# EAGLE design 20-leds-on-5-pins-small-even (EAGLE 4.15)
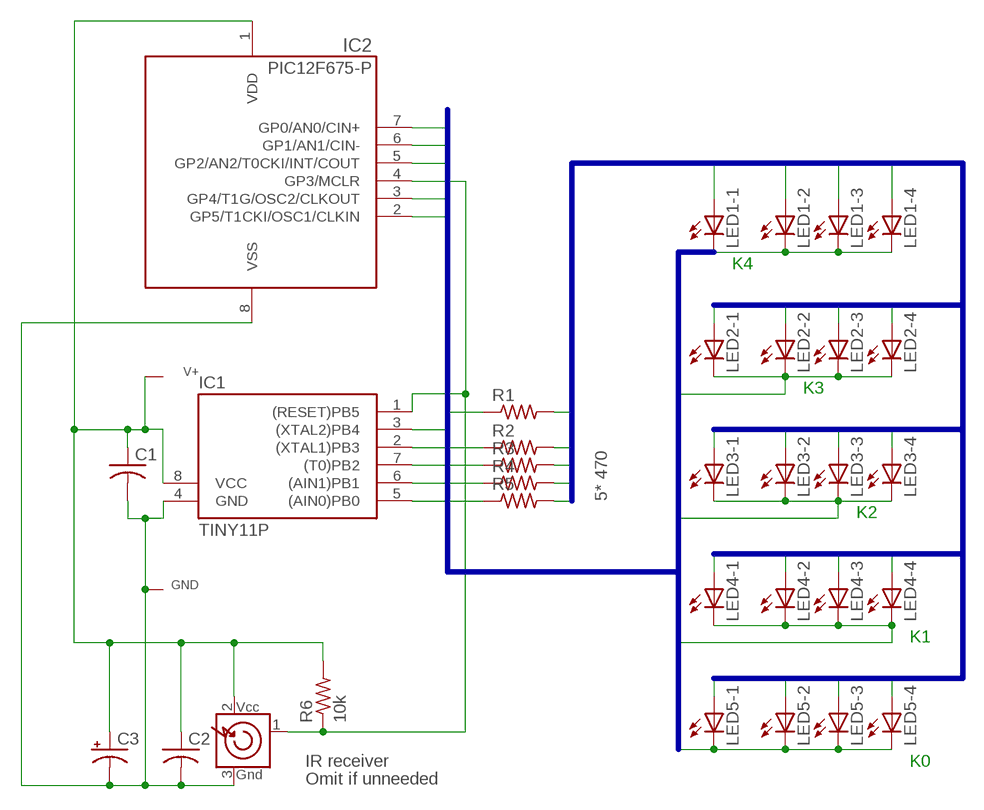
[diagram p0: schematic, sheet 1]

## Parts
C1  C-US075-032X103  [C075-032X103]
C2  C-US050-035X075  [C050-035X075]
C3  CPOL-USE3.5-8  [E3,5-8]
GND  WIRE  [GENERIC1]
IC1  TINY11P  [DIL08]
IC2  PIC12F675-P  [DIP-8]
IRX1  IRRECVV  [IR-RCVR-V]
LED1-1  LED3MM  [LED3MM]
LED1-2  LED3MM  [LED3MM]
LED1-3  LED3MM  [LED3MM]
LED1-4  LED3MM  [LED3MM]
LED2-1  LED3MM  [LED3MM]
LED2-2  LED3MM  [LED3MM]
LED2-3  LED3MM  [LED3MM]
LED2-4  LED3MM  [LED3MM]
LED3-1  LED3MM  [LED3MM]
LED3-2  LED3MM  [LED3MM]
LED3-3  LED3MM  [LED3MM]
LED3-4  LED3MM  [LED3MM]
LED4-1  LED3MM  [LED3MM]
LED4-2  LED3MM  [LED3MM]
LED4-3  LED3MM  [LED3MM]
LED4-4  LED3MM  [LED3MM]
LED5-1  LED3MM  [LED3MM]
LED5-2  LED3MM  [LED3MM]
LED5-3  LED3MM  [LED3MM]
LED5-4  LED3MM  [LED3MM]
R1  R-US_0204/2V  [0204V]
R2  R-US_0204/2V  [0204V]
R3  R-US_0204/2V  [0204V]
R4  R-US_0204/2V  [0204V]
R5  R-US_0204/2V  [0204V]
R6  10k  R-US_0204/2V  [0204V]
V+  WIRE  [GENERIC1]

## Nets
A0: LED1-1.A LED2-1.A LED3-1.A LED4-1.A R5.2
A1: LED1-2.A LED2-2.A LED3-2.A LED5-1.A R4.2
A2: LED1-3.A LED2-3.A LED4-2.A LED5-2.A R3.2
A3: LED1-4.A LED3-3.A LED4-3.A LED5-3.A R2.2
A4: LED2-4.A LED3-4.A LED4-4.A LED5-4.A R1.2
GND [power]: C1.2 C2.2 C3.- GND.P$2 IC1.4(GND) IC2.8(VSS) IRX1.3(GND)
K0: IC1.7((T0)PB2) IC2.7(GP0/AN0/CIN+) LED5-1.K(C) LED5-2.K(C) LED5-3.K(C) LED5-4.K(C) R5.1
K1: IC1.6((AIN1)PB1) IC2.6(GP1/AN1/CIN-) LED4-1.K(C) LED4-2.K(C) LED4-3.K(C) LED4-4.K(C) R4.1
K2: IC1.5((AIN0)PB0) IC2.5(GP2/AN2/T0CKI/INT/COUT) LED3-1.K(C) LED3-2.K(C) LED3-3.K(C) LED3-4.K(C) R3.1
K3: IC1.3((XTAL2)PB4) IC2.3(GP4/T1G/OSC2/CLKOUT) LED2-1.K(C) LED2-2.K(C) LED2-3.K(C) LED2-4.K(C) R2.1
K4: IC1.2((XTAL1)PB3) IC2.2(GP5/T1CKI/OSC1/CLKIN) LED1-1.K(C) LED1-2.K(C) LED1-3.K(C) LED1-4.K(C) R1.1
N$2: IC1.1((RESET)PB5) IC2.4(GP3/MCLR) IRX1.1(OUT) R6.1
V+ [power]: C1.1 C2.1 C3.+ IC1.8(VCC) IC2.1(VDD) IRX1.2(VCC) R6.2 V+.P$2

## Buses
K[0..4]
A[0..4]

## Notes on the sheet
- K4
- K3
- 5* 470
- K2
- K1
- IR receiver | K0
- Omit if unneeded

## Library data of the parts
C1 C2 = rcl:C-US: CAPACITOR, American symbol
C3 = rcl:CPOL-US: POLARIZED CAPACITOR, American symbol
GND V+ = mylib:WIRE: Pad for a wire offboard
IC1 = atmel:TINY11*: MICROCONTROLLER 1 Kbytes FLASH
IC2 = pic-olin:PIC12F675-?: 8 pins, 1K prog, 128 EEPROM, 1 comp, A/D
IRX1 = mylib:IRRECV: IR Reciver. Integrated for remote control. Vishay TSOP28
LED1-1-LED1-4 LED2-1-LED2-4 LED3-1-LED3-4 LED4-1-LED4-4 LED5-1-LED5-4 = led:LED: LED
R1-R6 = rcl:R-US_: RESISTOR, American symbol

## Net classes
0 default: width 0.5 mm
1 power: width 0.7 mm, drill 0.5 mm

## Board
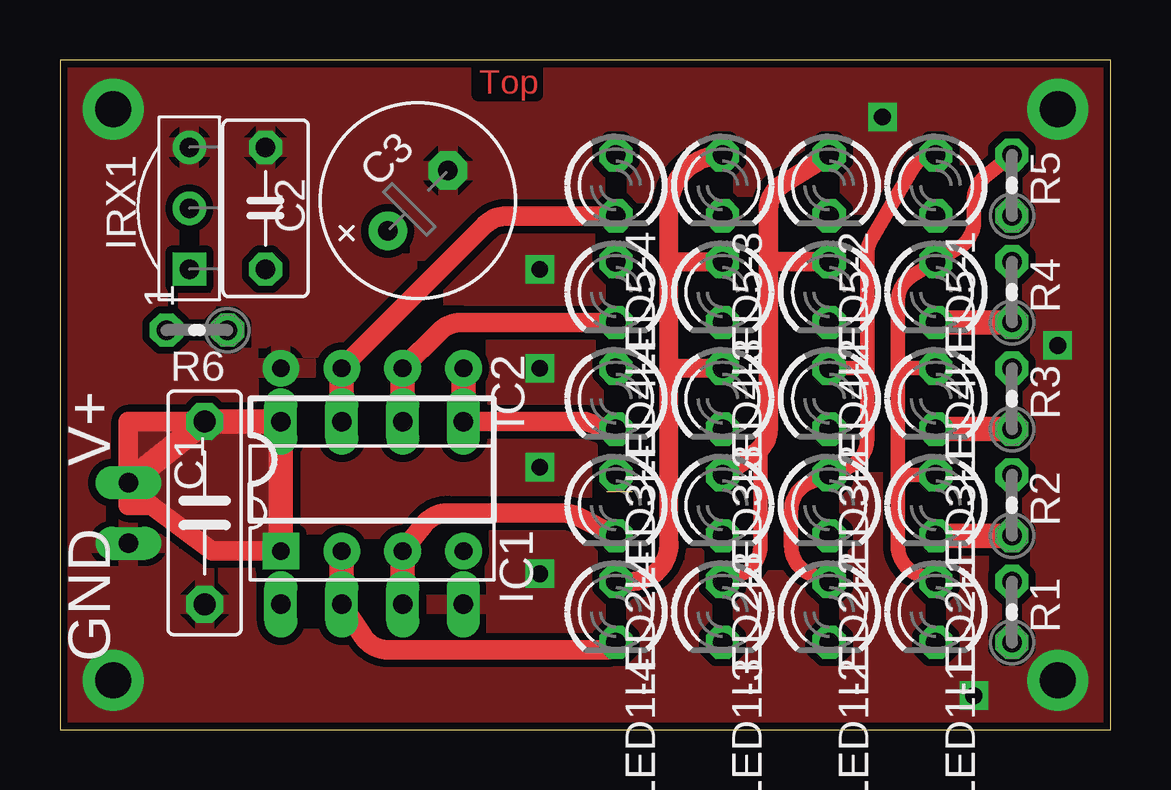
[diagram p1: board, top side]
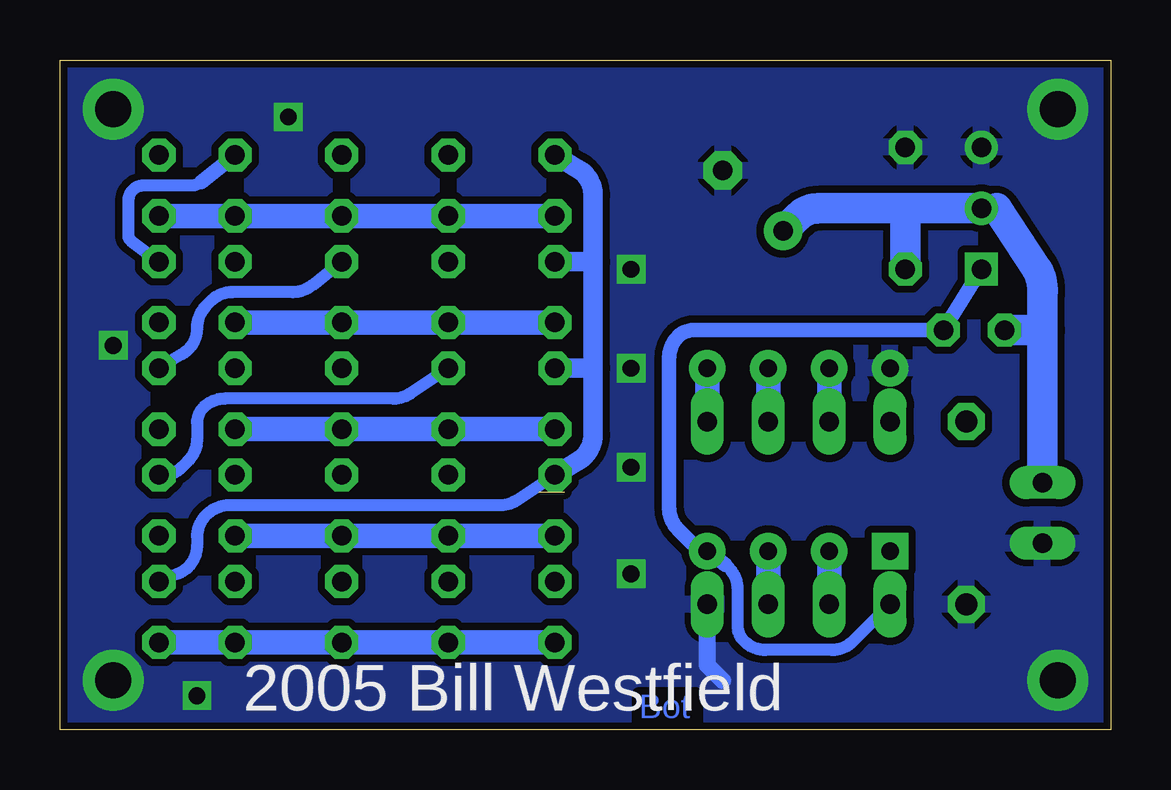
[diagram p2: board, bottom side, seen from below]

Size 43.81 x 27.93 mm. Coordinates in mm from the lower left corner, seen from the top.
Outline: 23.86,9.91 22.77,9.92
Outline: 43.81,0 43.81,27.93 0,27.93 0,0 43.81,0
Copper layers (1*16): Top 0.035mm / dielectric 1.5mm / Bottom 0.035mm
Design rules "default": minimum track width 10mil, minimum drill 0.7mm, track to track 0.3mm, track to pad 0.3mm, pad to pad 0.3mm, via to via 0.3mm, smd to smd 8mil, copper to edge 10mil, drill to drill 8mil, minimum pad ring 10mil, minimum via ring 8mil, stop-mask expansion 4mil, vias tented up to drill 0mil, thermal gap 10mil

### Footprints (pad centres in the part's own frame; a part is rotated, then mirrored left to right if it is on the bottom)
C075-032X103 = drill 0.914 octagon: 1 -3.81,0; 2 3.81,0
C050-035X075 = drill 0.813 octagon: 1 -2.54,0; 2 2.54,0
E3,5-8 = drill 0.813 pad 1.6 round: + -1.778,0 | drill 0.813 pad 1.6 octagon: - 1.778,0
GENERIC1 = drill 0.813 long: P$2 0,0
DIL08 = drill 0.813 long: 1 -3.81,-3.81; 2 -1.27,-3.81; 3 1.27,-3.81; 4 3.81,-3.81; 5 3.81,3.81; 6 1.27,3.81; 7 -1.27,3.81; 8 -3.81,3.81
DIP-8 = drill 0.737 pad 1.524 square: 1 -3.81,-3.81 | drill 0.737 pad 1.524 round: 2 -1.27,-3.81; 3 1.27,-3.81; 4 3.81,-3.81; 5 3.81,3.81; 6 1.27,3.81; 7 -1.27,3.81; 8 -3.81,3.81
IR-RCVR-V = drill 0.813 square: 1 2.54,0 | drill 0.813 round: 2 0,0; 3 -2.54,0
LED3MM = drill 0.813 octagon: A -1.27,0; K 1.27,0
0204V = drill 0.813 octagon: 1 -1.27,0; 2 1.27,0

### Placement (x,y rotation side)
C1  6.03,9.04 270 top
C2  8.57,21.74 90 top
C3  14.92,22.06 45 top
GND  2.85,7.77 0 top
IC1  13.01,9.04 0 top
IC2  13.01,11.27 0 top
IRX1  5.39,21.74 270 top
LED1-1  36.51,4.92 270 top
LED1-2  32.06,4.92 270 top
LED1-3  27.62,4.92 270 top
LED1-4  23.17,4.92 270 top
LED2-1  36.51,9.36 270 top
LED2-2  32.06,9.36 270 top
LED2-3  27.62,9.36 270 top
LED2-4  23.17,9.36 270 top
LED3-1  36.51,13.8 270 top
LED3-2  32.06,13.8 270 top
LED3-3  27.62,13.8 270 top
LED3-4  23.17,13.8 270 top
LED4-1  36.51,18.25 270 top
LED4-2  32.06,18.25 270 top
LED4-3  27.62,18.25 270 top
LED4-4  23.17,18.25 270 top
LED5-1  36.51,22.7 270 top
LED5-2  32.06,22.7 270 top
LED5-3  27.62,22.7 270 top
LED5-4  23.17,22.7 270 top
R1  39.68,4.92 90 top
R2  39.68,9.36 90 top
R3  39.68,13.8 90 top
R4  39.68,18.25 90 top
R5  39.68,22.7 90 top
R6  5.71,16.66 180 top
V+  2.85,10.31 0 top

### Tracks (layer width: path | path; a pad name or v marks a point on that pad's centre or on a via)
A0
  Top 0.61: LED1-1.A 35.72,6.5 arc-68 34.92,7.68 34.92,10.63 | 34.92,10.63 LED2-1.A | 34.92,10.63 34.92,15.07 | 34.92,15.07 34.92,17.85 arc-59 35.54,18.94 LED4-1.A 37.48,20.1 arc59 38.1,21.19 38.1,22.09 arc-51 38.57,23.08 R5.2 | 34.92,15.07 LED3-1.A
A1
  Top 0.61: LED1-2.A 31.27,6.5 arc-68 30.47,7.68 30.47,9.14 arc-68 31.27,10.31 LED2-2.A 32.85,10.95 arc68 33.65,12.12 33.65,15.07 | 33.65,15.07 33.65,19.81 arc-30 33.82,20.45 35.55,23.42 arc-60 LED5-1.A | 33.65,15.07 LED3-2.A
  Bottom 0.5: R4.2 40.85,20.4 arc53 40.95,20.6 40.95,22.06 arc90 40.32,22.7 38.32,22.7 arc-39 37.92,22.83
  Bottom 0.61: LED5-1.A 37.92,22.83
A2
  Top 0.5: 29.2,11.58 LED2-3.A
  Top 0.61: LED1-3.A 28.41,6.5 arc68 29.2,7.68 29.2,11.58
  Top 0.813: 29.52,19.52 29.52,21.67 arc-58 30.12,22.75 LED5-2.A | LED2-3.A 28.96,11.52 arc56 29.52,12.58 29.52,19.52 | 29.52,19.52 LED4-2.A
  Bottom 0.5: LED4-2.A 33.3,18.53 arc39 34.1,18.25 36.62,18.25 arc-45 37.52,17.88 37.72,17.67 arc-45 38.1,16.77 38.1,16.75 arc59 38.71,15.66 R3.2
A3
  Top 0.8: LED1-4.A 23.81,6.19 arc90 25.39,7.77 25.39,15.07 | 25.39,15.07 25.39,19.52 | 25.39,19.52 25.39,21.74 arc-90 LED5-3.A | 25.39,19.52 LED4-3.A | 25.39,15.07 LED3-3.A
  Bottom 0.5: LED3-3.A 29.2,14.02 arc34 29.91,13.8 36.93,13.8 arc-45 37.83,13.43 arc-45 38.1,12.8 38.1,12.11 arc45 38.47,11.21 38.76,10.92 arc45 39.46,10.63 R2.2
A4
  Bottom 0.5: R1.2 38.89,6.5 arc-68 38.1,7.68 38.1,8.05 arc56 37.53,9.1 37.46,9.15 arc34 36.76,9.36 25.46,9.36 arc-34 24.76,9.57 LED2-4.A
  Bottom 0.813: LED2-4.A 22.2,11.21 arc-59 21.59,12.3 21.59,15.07 | 21.59,15.07 LED3-4.A | 21.59,19.52 LED4-4.A | 21.59,15.07 21.59,19.52 | 21.59,19.52 21.59,22.29 arc-59 22.2,23.38 LED5-4.A
GND  (via drill 0.7, 1.5)
  Bottom 0.7: 16.19,2.06 16.82,2.69 IC1.4
  other vias: 20,10.95 20,15.07 2.22,25.87 2.22,2.06 41.59,2.06 41.59,25.87 20,19.2 20,6.5 34.29,25.55 38.1,1.42 41.59,16.03
  pour Bottom (isolate 0.305): -2.23,28.73 -2.23,-0.8 45.4,-1.12 45.4,28.41
  pour Top (isolate 0.305): -0.96,28.73 -0.96,-0.8 44.45,-0.8 44.45,28.73
K0
  Top 0.813: IC2.7 17.72,21.05 arc-45 18.62,21.43 LED5-4.K
  Top 1.016: IC1.7 IC2.7
  Bottom 1.016: R5.1 LED5-1.K LED5-2.K LED5-3.K LED5-4.K | IC1.7 IC2.7
K1
  Top 0.813: IC2.6 15.82,16.61 arc-45 16.71,16.98 LED4-4.K
  Top 1.016: LED4-1.K R4.1 | IC1.6 IC2.6
  Bottom 1.016: LED4-1.K LED4-2.K LED4-3.K LED4-4.K | IC1.6 IC2.6
K2
  Top 0.813: IC1.5 21.9,12.85 22.86,12.54 LED3-4.K
  Top 1.016: LED3-1.K R3.1 | IC1.5 IC2.5
  Bottom 1.016: LED3-1.K LED3-2.K LED3-3.K LED3-4.K | IC1.5 IC2.5
K3
  Top 0.813: IC2.3 15.17,8.57 arc-51 16.16,9.04 20.97,9.04 arc-27 21.54,8.91 LED2-4.K
  Top 1.016: LED2-1.K R2.1 | IC1.3 IC2.3
  Bottom 1.016: LED2-1.K LED2-2.K LED2-3.K LED2-4.K | IC1.3 IC2.3
K4
  Top 0.813: IC1.2 12.64,3.89 arc56 13.69,3.33 22.86,3.33 LED1-4.K
  Top 1.016: IC1.2 IC2.2
  Bottom 1.016: R1.1 LED1-1.K LED1-2.K LED1-3.K LED1-4.K | IC1.2 11.74,7.14
N$2
  Bottom 0.5: IC1.1 10.74,3.7 arc45 11.63,3.33 14.39,3.33 arc45 15.29,3.7 arc45 15.55,4.33 15.55,5.87 arc-53 16.06,6.88 | 10.15,16.66 9.84,16.66
  Bottom 0.61: 16.06,6.88 IC2.4 | IC2.4 17.14,7.14 | IC2.4 17.46,7.77 18.04,8.35 arc45 18.41,9.25 18.41,15.5 arc45 18.04,16.4 arc45 17.4,16.66 10.15,16.66 R6.1 IRX1.1
V+
  Top 0.813: V+.P$2 2.85,12.85 C1.1 IC1.8 IC2.1 6.35,7.46 3.8,9.36 2.85,9.36 V+.P$2
  Top 1.016: V+.P$2 C1.1 IC1.8 IC2.1
  Bottom 0.7: 4.76,21.74 IRX1.2
  Bottom 1.27: V+.P$2 2.85,16.66 | 2.85,16.66 2.85,18.17 arc-35 3.08,19.21 4.76,21.74 | 2.85,16.66 R6.2 | 8.57,21.75 6.33,21.75 IRX1.2 | 8.57,21.75 12.17,21.74 arc-45 13.06,21.37 13.63,20.8 C3.+ | 8.57,21.75 8.57,21.11 | 8.57,21.75 C2.1
  pour Top (isolate 0.4, no thermals): 3.17,12.54 3.17,9.68 4.44,9.68 6.35,8.09 8.57,8.09 8.57,12.54

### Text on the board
Top: Top
Bottom: Bot
bPlace: 2005 Bill Westfield
tValues: 470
